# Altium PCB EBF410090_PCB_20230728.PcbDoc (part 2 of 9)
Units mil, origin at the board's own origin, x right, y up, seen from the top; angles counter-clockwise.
Board outline 5393.69 x 3858.26 mil, 6 copper layers (TOP, GND02, ART03, ART04, PWR05, BOTTOM), stack 47.2 mil thick; 570 components, 437 nets, 2015 pads, 1260 vias.
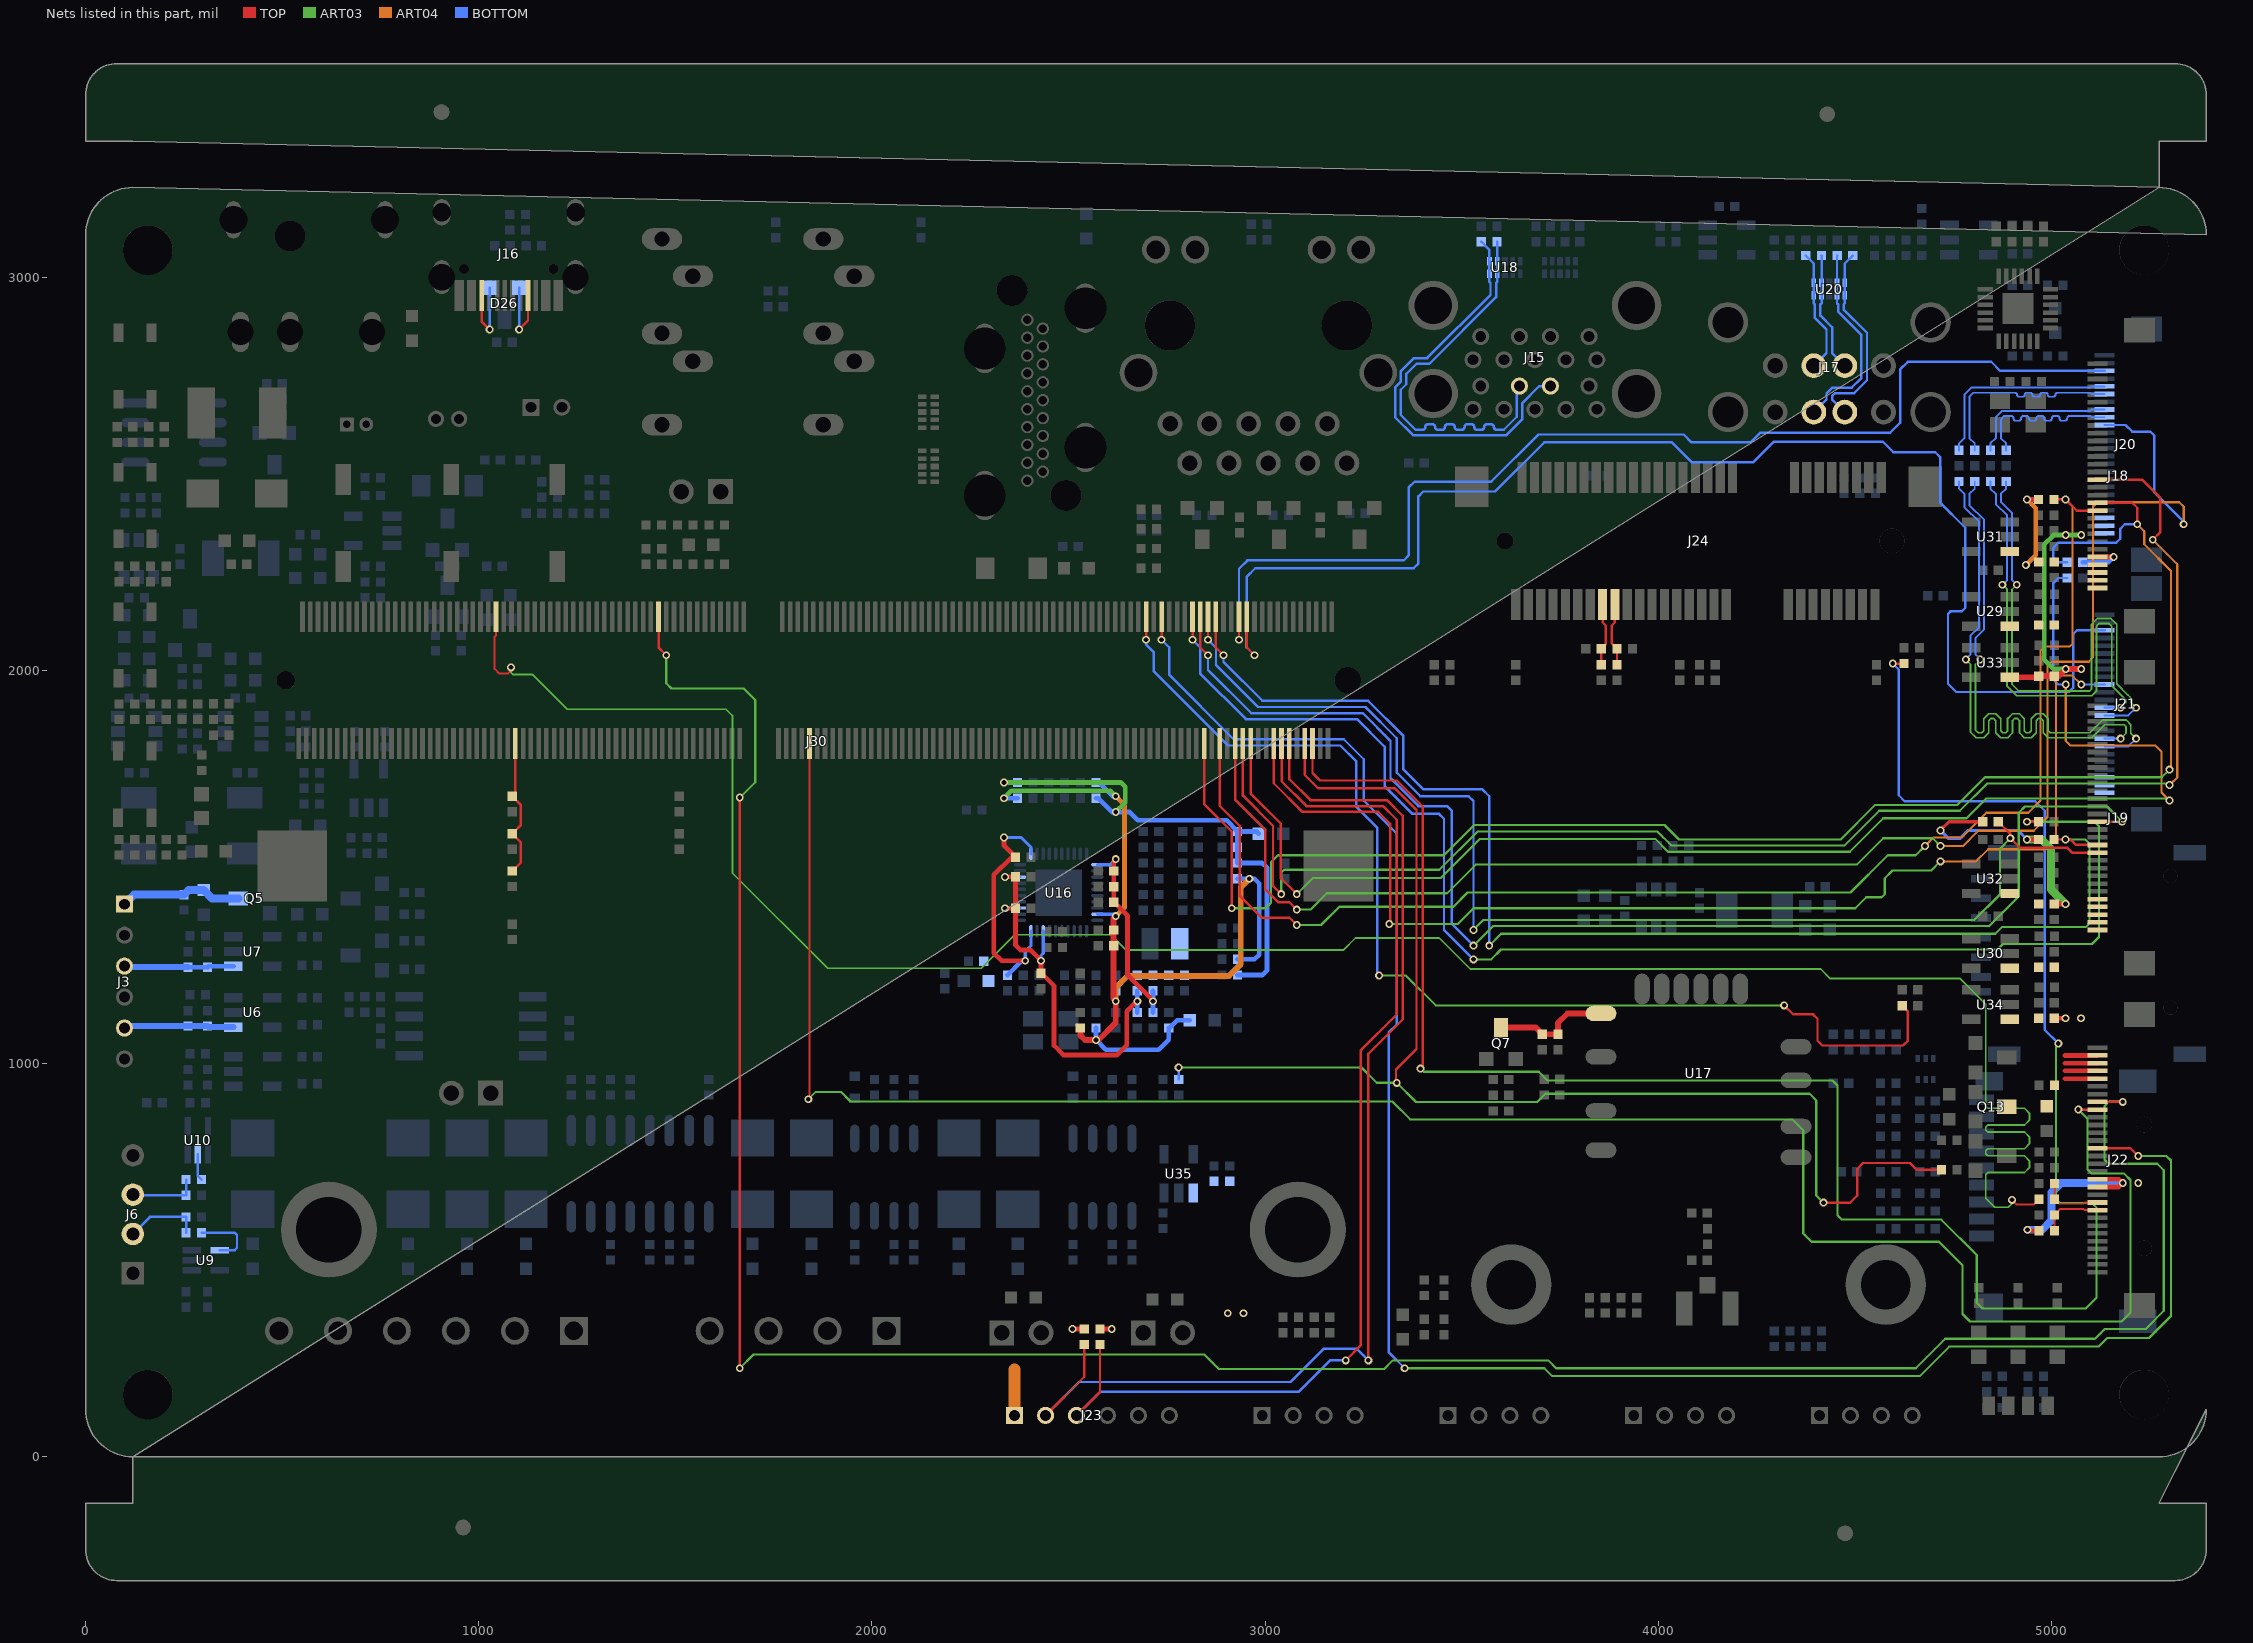
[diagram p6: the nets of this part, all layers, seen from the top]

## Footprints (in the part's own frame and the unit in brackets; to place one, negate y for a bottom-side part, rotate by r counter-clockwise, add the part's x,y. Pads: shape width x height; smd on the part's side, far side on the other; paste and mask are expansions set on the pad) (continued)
DB2ERC-3P81-4P [mil] "DB2ERC-3P81-4P"
  rect 70.87x70.87 / inner round 60 / far side rect 70.87x70.87 hole 47.24: 1(-225.39,-137.79)
  round 70.87 / inner round 60 / far side round 70.87 hole 47.24: 2(-75.39,-137.79) 3(74.61,-137.79) 4(224.61,-137.79)
  silkscreen extent -354,-181 319,179, body extent -323,-185 323,185, height 150
DB2ERC-3P81-6P [mil] "DB2ERC-3P81-6P"
  rect 70.87x70.87 / inner round 60 / far side rect 70.87x70.87 hole 47.24: 1(-375,-137.79)
  round 70.87 hole 47.24: 2(-225,-137.79) 5(225,-137.79)
  round 70.87 / inner round 60 / far side round 70.87 hole 47.24: 3(-75,-137.79) 4(75,-137.79) 6(375,-137.79)
  silkscreen extent -503,-181 470,179, body extent -472,-185 472,185, height 150
DC_IN_TH_3P_10R1X11R6 [mil] "DC_IN_TH_3P_10R1X11R6"
  oval 94.5x39.4 hole 70.9 slot 15.7 at 90 deg: 1(-111.25,-194.9) 5(-111.25,190.9)
  oval 102.4x43.3 hole 66.9 slot 19.7 at 90 deg: 2(174.25,-51.2) 3(174.25,157.4)
  oval 102.4x43.3 / inner round 60 / far side oval 102.4x43.3 hole 66.9 slot 19.7 at 90 deg: 4(174.25,-177.2)
  round 78.7 hole 78.7 unplated: ""(-69.85,-51.2)
  silkscreen extent -232,-201 226,197, body extent -237,-228 237,228, height 150
EAR_JACK [mm] "EAR_JACK"
  oval 1.4x2.6 / inner round 1.524 / far side oval 1.4x2.6 hole 1 slot 2 at 90 deg: 1(-5.904,-0.05) 2(-3.504,1.95) 3(1.996,1.95) 4(6.096,-0.05) 5(0.196,-0.05)
  silkscreen extent -11.12,-4.06 7.2,4.06, body extent -7.2,-4.15 7.2,4.15, height 3.81
EC6P3 [mil] "EC6P3"
  rect 39.4x78.7 smd: 1(0,110.24) 2(0,-110.24)
  silkscreen extent -130,-130 130,130, body extent -138,-157 138,157, height 150
ES0402#1 [mil] "ES0402"
  rect 23.6x23.6 smd: 1(-19.68,0) 2(19.68,0)
  silkscreen extent -37,-17 37,17, body extent -37,-17 37,17, height 150
ES0402#2 [mil] "ES0402"
  rect 23.6x23.6 smd: 1(19.68,0) 2(-19.68,0)
  silkscreen extent -37,-17 37,17, body extent -37,-17 37,17, height 150
F1812 [mil] "F1812"
  rect 70.08x129.92 smd: 1(-90.75,0) 2(90.75,0)
  silkscreen extent -134,-75 134,75
FPC-30P-0P5 [mm] "FPC-30P-0P5"
  rect 0.3x1.3 smd: 1(-7.25,2.733) 2(-6.75,2.733) 3(-6.25,2.733) 4(-5.75,2.733) 5(-5.25,2.733) 6(-4.75,2.733) 7(-4.25,2.733) 8(-3.75,2.733) 9(-3.25,2.733) 10(-2.75,2.733) 11(-2.25,2.733) 12(-1.75,2.733) 13(-1.25,2.733) 14(-0.75,2.733) 15(-0.25,2.733) 16(0.25,2.733) 17(0.75,2.733) 18(1.25,2.733) 19(1.75,2.733) 20(2.25,2.733) 21(2.75,2.733) 22(3.25,2.733) 23(3.75,2.733) 24(4.25,2.733) 25(4.75,2.733) 26(5.25,2.733) 27(5.75,2.733) 28(6.25,2.733) 29(6.75,2.733) 30(7.25,2.733)
  rect 1.6x2 smd: 31(9.4,0.033) 32(-9.4,0.033)
  silkscreen extent -10.05,-3.27 10.05,4.14, body extent -10.05,-3.35 10.05,3.35, height 3.81
FPC_24P_0P5 [mm] "FPC_24P_0P5"
  rect 0.3x1.3 smd: 1(-5.75,-2.701) 2(-5.25,-2.701) 3(-4.75,-2.701) 4(-4.25,-2.701) 5(-3.75,-2.701) 6(-3.25,-2.701) 7(-2.75,-2.701) 8(-2.25,-2.701) 9(-1.75,-2.701) 10(-1.25,-2.701) 11(-0.75,-2.701) 12(-0.25,-2.701) 13(0.25,-2.701) 14(0.75,-2.701) 15(1.25,-2.701) 16(1.75,-2.701) 17(2.25,-2.701) 18(2.75,-2.701) 19(3.25,-2.701) 20(3.75,-2.701) 21(4.25,-2.701) 22(4.75,-2.701) 23(5.25,-2.701) 24(5.75,-2.701)
  rect 1.6x2 smd: 25(7.45,0.001) 26(-7.45,0.001)
  silkscreen extent -8.1,-3.95 8.1,3.35
GH1P25_TH_2P [mil] "GH1P25_TH_2P"
  rect 35.43x35.43 / inner round 60 / far side rect 35.43x35.43 hole 19.69: 1(-24.65,-33.42)
  round 35.43 hole 19.69: 2(24.57,-33.42)
  silkscreen extent -87,-69 87,69
HDMI-SMD [mil] "HDMI-SMD"
  round 31.5 / inner round 60 / far side round 31.5 hole 21.65: 1(50.23,19.69) 3(4.76,19.69) 4(-17.68,-19.68) 6(-63.19,-19.68) 7(-86.18,19.69) 9(-131.65,19.69) 10(-154.21,-19.68) 12(-199.72,-19.68) 13(-222.6,19.69) 14(-245.23,-19.68) 15(-268.08,19.69) 16(-290.75,-19.68) 18(-336.26,-19.68) 19(-359.01,19.69)
  round 31.5 hole 21.65: 2(27.84,-19.68) 5(-40.71,19.69) 8(-108.7,-19.68) 11(-177.13,19.69) 17(-313.54,19.69)
  oval 125.98x55.12 / inner round 60 / far side oval 125.98x55.12 hole 106.3 slot 35.43 at 90 deg: G1(-396.62,127.96) G2(-22.6,127.96) G3(-274.57,-127.95) G4(79.77,-127.95)
  round 78.7 hole 78.7 unplated: ""(-396.62,-78.74) ""(125.03,59.06)
  silkscreen extent -450,-151 465,149, body extent -464,-160 464,160, height 150
HDR1X2-2R54-TM-VM#1 [mm] "HDR1X2-2R54-TM-VM"
  rect 1.6x1.6 hole 1: 1(1.27,0)
  round 1.6 / inner round 1.524 / far side round 1.6 hole 1: 2(-1.27,0)
  silkscreen extent -2.54,-1.25 2.54,1.25, body extent -2.54,-1.25 2.54,1.25, height 3.81
HDR1X2-2R54-TM-VM#2 [mm] "HDR1X2-2R54-TM-VM"
  rect 1.6x1.6 / inner round 1.524 / far side rect 1.6x1.6 hole 1: 1(-1.27,0)
  round 1.6 / inner round 1.524 / far side round 1.6 hole 1: 2(1.27,0)
  silkscreen extent -2.54,-1.25 2.54,1.25, body extent -2.54,-1.25 2.54,1.25, height 3.81
HY911130A [mm] "HY911130A"
  round 1.6 / inner round 1.524 / far side round 1.6 hole 1: 1(5.72,-8.79) 2(4.45,-6.25) 3(3.18,-8.79) 4(1.91,-6.25) 5(0.64,-8.79) 6(-0.63,-6.25) 7(-1.9,-8.79) 8(-3.17,-6.25) 9(-4.44,-8.79)
  round 1.6 hole 1: 10(-5.71,-6.25)
  round 1.8 / inner round 1.524 / far side round 1.8 hole 1.2: 11(6.625,5) 12(4.085,5) 13(-4.085,5) 14(-6.625,5)
  round 2.43 hole 1.83: 15(7.745,-2.95) 16(-7.745,-2.95)
  round 3.25 hole 3.25 unplated: ""(-5.715,0.1) ""(5.715,0.1)
  silkscreen extent -8.02,-10.3 8.02,11, body extent -9.2,-11.1 9.2,11.1, height 3.81
L0603#1 [mil] "L0603"
  rect 31.5x31.5 smd: 1(-31.5,0) 2(31.5,0)
  silkscreen extent -54,-24 55,24, body extent -47,-16 47,16, height 150
L0603#2 [mil] "L0603"
  rect 31.5x31.5 smd: 1(31.5,0) 2(-31.5,0)
  silkscreen extent -55,-24 54,24, body extent -47,-16 47,16, height 150
L2520 [mil] "L2520"
  rect 44x80 smd: 1(-37.75,0) 2(37.75,0)
  silkscreen extent -68,-48 68,48, body extent -65,-45 65,45, height 150
L4520 [mil] "L4520"
  rect 55.12x90.55 smd: 1(-70.97,-0.1) 2(70.77,-0.1)
  silkscreen extent -91,-87 90,87, body extent -91,-87 91,87, height 150
LED0603 [mil] "LED0603"
  rect 36.61x38.58 smd: 1(30.32,0) 2(-30.31,0)
  silkscreen extent -60,-31 80,31, body extent -49,-19 49,19, height 150
MARK#1 [mil] "MARK"
  round 40 smd: 1(0,0) 1(3571,3616)
  round 40 smd far side: 1(0,1) 1(55,3601) 1(3525,6) 1(3570,3616)
  body extent -40,-40 3611,3656, height 150
MARK#2 [mil] "MARK"
  round 40 smd: 1(-55,-3601) 1(3516,15)
  round 40 smd far side: 1(-55,-3600) 1(0,0) 1(3470,-3595) 1(3515,15)
  body extent -95,-3641 3556,55, height 150
MARK#3 [mil] "MARK"
  round 40 smd: 1(-3525,-6) 1(46,3610)
  round 40 smd far side: 1(-3525,-5) 1(-3470,3595) 1(0,0) 1(45,3610)
  body extent -3565,-46 86,3650, height 150
MARK#4 [mil] "MARK"
  round 40 smd: 1(-3571,-3616) 1(0,0)
  round 40 smd far side: 1(-3571,-3615) 1(-3516,-15) 1(-46,-3610) 1(-1,0)
  body extent -3611,-3656 40,40, height 150
MARK#5 [mil] "MARK"
  round 40 smd: 1(-3570,3615) 1(-3515,15) 1(-45,3610) 1(0,0)
  round 40 smd far side: 1(-3570,3616) 1(1,0)
  body extent -3610,-40 41,3656, height 150
MARK#6 [mil] "MARK"
  round 40 smd: 1(-55,3600) 1(0,0) 1(3470,3595) 1(3515,-15)
  round 40 smd far side: 1(-55,3601) 1(3516,-15)
  body extent -95,-55 3556,3641, height 150
MARK#7 [mil] "MARK"
  round 40 smd: 1(-3525,5) 1(-3470,-3595) 1(0,0) 1(45,-3610)
  round 40 smd far side: 1(-3525,6) 1(46,-3610)
  body extent -3565,-3650 86,46, height 150
MARK#8 [mil] "MARK"
  round 40 smd: 1(0,0) 1(55,-3600) 1(3525,-5) 1(3570,-3615)
  round 40 smd far side: 1(0,1) 1(3571,-3615)
  body extent -40,-3655 3611,41, height 150
NANO_SIM [mm] "NANO_SIM"
  rect 0.5x1.3 smd: 1(0.25,6.94) 2(-2.29,6.94) 3(-4.83,6.94) 4(2.47,6.94) 5(1.52,6.94) 6(-1.02,6.94) 7(-3.56,6.94)
  rect 1x2.1 smd: 8(-6.5,5.46) 9(6.5,5.46) 10(-6.5,-6.54) 11(6.5,-6.54)
  round 0.9 hole 0.9 unplated: ""(-5,-5.29) ""(3.5,-5.29)
  silkscreen extent -6.15,-7.6 6.15,5.9, body extent -7.05,-7.64 7.05,7.64, height 3.81
NPTH_M3 [mil] "NPTH_M3"
  round 125.98 / inner round 60 / far side round 125.98 hole 125.98 unplated: 1(0,0)
  body extent -122,-122 122,122, height 150
PCIE_52P [mm] "PCIE_52P"
  rect 0.6x2 smd: 1(-11.8,-4.1) 2(-11.4,4.1) 3(-11,-4.1) 4(-10.6,4.1) 5(-10.2,-4.1) 6(-9.8,4.1) 7(-9.4,-4.1) 8(-9,4.1) 9(-8.6,-4.1) 10(-8.2,4.1) 11(-7.8,-4.1) 12(-7.4,4.1) 13(-7,-4.1) 14(-6.6,4.1) 15(-6.2,-4.1) 16(-5.8,4.1) 17(-2.2,-4.1) 18(-1.8,4.1) 19(-1.4,-4.1) 20(-1,4.1) 21(-0.6,-4.1) 22(-0.2,4.1) 23(0.2,-4.1) 24(0.6,4.1) 25(1,-4.1) 26(1.4,4.1) 27(1.8,-4.1) 28(2.2,4.1) 29(2.6,-4.1) 30(3,4.1) 31(3.4,-4.1) 32(3.8,4.1) 33(4.2,-4.1) 34(4.6,4.1) 35(5,-4.1) 36(5.4,4.1) 37(5.8,-4.1) 38(6.2,4.1) 39(6.6,-4.1) 40(7,4.1) 41(7.4,-4.1) 42(7.8,4.1) 43(8.2,-4.1) 44(8.6,4.1) 45(9,-4.1) 46(9.4,4.1) 47(9.8,-4.1) 48(10.2,4.1) 49(10.6,-4.1) 50(11,4.1) 51(11.4,-4.1) 52(11.8,4.1)
  rect 2.15x2.6 smd: 53(14.65,-3.5) 54(-14.65,-3.5)
  round 1.6 hole 1.6 unplated: ""(-12.5,0)
  round 1.1 hole 1.1 unplated: ""(12.5,0)
  silkscreen extent -15,-4.6 15,50.95, body extent -15.8,-5.2 15.8,5.2, height 3.81
PH-1X2-2P0_L [mm] "PH-1X2-2P0_L"
  rect 1.1x1.1 / inner round 1.524 / far side rect 1.1x1.1 hole 0.7: 1(-1,-0.6)
  round 1.1 / inner round 1.524 / far side round 1.1 hole 0.7: 2(1,-0.6)
  silkscreen extent -3,-2.6 3,2.6, body extent -3.1,-2.7 3.1,2.7, height 3.81
PH-1X4-2P0 [mm] "PH-1X4-2P0"
  rect 1.1x1.1 / inner round 1.524 / far side rect 1.1x1.1 hole 0.7: 1(-3,-0.6)
  round 1.1 / inner round 1.524 / far side round 1.1 hole 0.7: 2(-1,-0.6) 3(1,-0.6)
  round 1.1 hole 0.7: 4(3,-0.6)
  silkscreen extent -5,-2.6 5,2.6, body extent -5.1,-2.7 5.1,2.7, height 3.81
PH-1X6-2P0#1 [mm] "PH-1X6-2P0"
  rect 1.1x1.1 / inner round 1.524 / far side rect 1.1x1.1 hole 0.7: 1(-5,-0.6)
  round 1.1 hole 0.7: 2(-3,-0.6) 4(1,-0.6) 6(5,-0.6)
  round 1.1 / inner round 1.524 / far side round 1.1 hole 0.7: 3(-1,-0.6) 5(3,-0.6)
  silkscreen extent -7,-2.6 7,2.6, body extent -7.1,-2.7 7.1,2.7, height 3.81
PH-1X6-2P0#2 [mm] "PH-1X6-2P0"
  rect 1.1x1.1 / inner round 1.524 / far side rect 1.1x1.1 hole 0.7: 1(-5,-0.6)
  round 1.1 / inner round 1.524 / far side round 1.1 hole 0.7: 2(-3,-0.6) 3(-1,-0.6) 4(1,-0.6) 5(3,-0.6)
  round 1.1 hole 0.7: 6(5,-0.6)
  silkscreen extent -7,-2.6 7,2.6, body extent -7.1,-2.7 7.1,2.7, height 3.81
QFN24 [mm] "QFN24"
  rect 1x0.3 smd: 1(-2.1,1.25) 2(-2.1,0.75) 3(-2.1,0.25) 4(-2.1,-0.25) 5(-2.1,-0.75) 6(-2.1,-1.25) 13(2.1,-1.25) 14(2.1,-0.75) 15(2.1,-0.25) 16(2.1,0.25) 17(2.1,0.75) 18(2.1,1.25)
  rect 0.3x1 smd: 7(-1.25,-2.1) 8(-0.75,-2.1) 9(-0.25,-2.1) 10(0.25,-2.1) 11(0.75,-2.1) 12(1.25,-2.1) 19(1.25,2.1) 20(0.75,2.1) 21(0.25,2.1) 22(-0.25,2.1) 23(-0.75,2.1) 24(-1.25,2.1)
  rect 2x2 smd: 25(0,0)
  silkscreen extent -2.79,-2.1 2.1,2.1, body extent -2.7,-2.7 2.7,2.7, height 3.81
QFP_40P_R [mil] "QFP_40P_R"
  oval 31.5x8.66 smd: 1(-98.43,70.87) 2(-98.43,55.12) 3(-98.43,39.37) 4(-98.43,23.62) 5(-98.43,7.87) 6(-98.43,-7.87) 7(-98.43,-23.62) 8(-98.43,-39.37) 9(-98.43,-55.12) 10(-98.43,-70.87) 21(98.43,-70.87) 22(98.43,-55.12) 23(98.43,-39.37) 24(98.43,-23.62) 25(98.43,-7.87) 26(98.43,7.87) 27(98.43,23.62) 28(98.43,39.37) 29(98.43,55.12) 30(98.43,70.87)
  oval 8.66x31.5 smd: 11(-70.87,-98.43) 12(-55.12,-98.43) 13(-39.37,-98.43) 14(-23.62,-98.43) 15(-7.87,-98.43) 16(7.87,-98.43) 17(23.62,-98.43) 18(39.37,-98.43) 19(55.12,-98.43) 20(70.87,-98.43) 31(70.87,98.43) 32(55.12,98.43) 33(39.37,98.43) 34(23.62,98.43) 35(7.87,98.43) 36(-7.87,98.43) 37(-23.62,98.43) 38(-39.37,98.43) 39(-55.12,98.43) 40(-70.87,98.43)
  rect 118.11x118.11 smd: 41(0,0)
  silkscreen extent -130,-98 98,110, body extent -116,-116 116,116, height 150
R0402#1 [mil] "R0402"
  rect 23.6x23.6 smd: 1(19.68,0) 2(-19.68,0)
  silkscreen extent -37,-17 37,17, body extent -37,-17 37,17, height 150
R0402#2 [mil] "R0402"
  rect 23.6x23.6 smd: 1(-19.68,0) 2(19.68,0)
  silkscreen extent -37,-17 37,17, body extent -37,-17 37,17, height 150
R0603#1 [mil] "R0603"
  rect 31.5x31.5 smd: 1(-31.5,0) 2(31.5,0)
  silkscreen extent -54,-24 55,24
R0603#2 [mil] "R0603"
  rect 31.5x31.5 smd: 1(31.5,0) 2(-31.5,0)
  silkscreen extent -55,-24 54,24, body extent -47,-16 47,16, height 150
RL-UM02WBS-8723BU [mm] "RL-UM02WBS-8723BU"
  oval 2x1 smd: 1(-6.3,4.122) 2(-6.3,2.122) 3(-6.3,-0.858) 4(-6.3,-3.018) 5(6.3,3.652) 6(6.3,1.122) 7(6.3,-2.378) 8(6.3,-5.178)
  oval 1x2 smd: 9(3.65,-6.748) 10(2.38,-6.748) 11(1.11,-6.748) 12(-0.16,-6.748) 13(-1.43,-6.748) 14(-2.7,-6.748)
  silkscreen extent -6.1,-6.55 6.1,6.45, body extent -6.1,-6.45 6.1,6.45, height 3.81
SMA214-CA [mil] "SMA214-CA"
  rect 82.68x70.87 smd: 1(-86.61,0) 2(86.61,0)
  silkscreen extent -87,-51 87,51, body extent -130,-55 130,55, height 150
SMB-CA [mil] "SMB-CA"
  rect 94.49x110.24 smd: 1(-90.55,0) 2(90.55,0)
  silkscreen extent -91,-71 91,71, body extent -138,-71 138,71, height 150
SMD4-6R80X2R50 [mil] "SMD4-6R80X2R50"
  rect 31.5x47.24 smd: 1(75,-27.56) 2(25,-27.56) 3(-25,-27.56) 4(-75,-27.56)
  silkscreen extent -134,-88 134,51, body extent -142,-59 142,59, height 150
SMTSO-M2R5 [mil] "SMTSO-M2R5"
  round 244.09 / inner round 204.72 / far side round 204.72 hole 166.14: 1(0,0)
  body extent -126,-126 126,126, height 150
SOD523 [mil] "SOD523"
  rect 23.62x27.56 smd: 1(-27.95,0) 2(27.95,0)
  silkscreen extent -51,-20 24,20, body extent -43,-16 43,16, height 150
SOD-123 [mil] "SOD-123"
  rect 47.24x55.12 smd: 1(66.93,0) 2(-66.93,0)
  silkscreen extent -71,-35 71,35, body extent -94,-39 94,39, height 150
SOIC8-208 [mil] "SOIC8-208"
  rect 70x25 smd: 1(157.48,-75) 2(157.48,-25) 3(157.48,25) 4(157.48,75) 5(-157.48,75) 6(-157.48,25) 7(-157.48,-25) 8(-157.48,-75)
  silkscreen extent -100,-104 224,104, body extent -197,-110 197,110, height 150
SOIC16 [mil] "SOIC16"
  oval 80x24 smd: 1(-109.8,174.8) 2(-109.8,125.2) 3(-109.8,74.8) 4(-109.8,25.2) 5(-109.8,-25.2) 6(-109.8,-74.8) 7(-109.8,-125.2) 8(-109.8,-174.8) 9(109.8,-174.8) 10(109.8,-125.2) 11(109.8,-74.8) 12(109.8,-25.2) 13(109.8,25.2) 14(109.8,74.8) 15(109.8,125.2) 16(109.8,174.8)
  silkscreen extent -179,-197 59,197, body extent -157,-205 157,205, height 150
SOP8#1 [mil] "SOP8"
  oval 23.62x70.87 smd: 1(-75,-98.43) 2(-25,-98.43) 3(25,-98.43) 4(75,-98.43) 5(75,98.43) 6(25,98.43) 7(-25,98.43) 8(-75,98.43)
  silkscreen extent -98,-164 98,55, body extent -98,-138 98,138, height 150
SOP8#2 [mil] "SOP8"
  oval 23.62x70.87 smd: 1(75,98.43) 2(25,98.43) 3(-25,98.43) 4(-75,98.43) 5(-75,-98.43) 6(-25,-98.43) 7(25,-98.43) 8(75,-98.43)
  silkscreen extent -98,-55 114,141, body extent -98,-138 98,138, height 150
SOT23#1 [mil] "SOT23"
  rect 36x36 smd: 1(-37.5,-43.5) 2(37.5,-43.5)
  rect 36x50 smd: 3(0,36.5)
  silkscreen extent -55,-54 55,36, body extent -56,-62 56,62, height 150
SOT23#2 [mil] "SOT23"
  rect 36x36 smd: 1(37.5,43.5) 2(-37.5,43.5)
  rect 36x50 smd: 3(0,-36.5)
  silkscreen extent -55,-36 55,54, body extent -56,-62 56,62, height 150
SOT23-5#1 [mil] "SOT23-5"
  rect 23.6x47.2 smd: 1(-37.4,-49.21) 2(0,-49.21) 3(37.4,-49.21) 4(37.4,49.21) 5(-37.4,49.21)
  silkscreen extent -70,-80 59,35, body extent -63,-75 63,75, height 150
SOT23-5#2 [mil] "SOT23-5"
  rect 23.6x47.2 smd: 1(37.4,49.21) 2(0,49.21) 3(-37.4,49.21) 4(-37.4,-49.21) 5(37.4,-49.21)
  silkscreen extent -59,-35 59,101, body extent -63,-75 63,75, height 150
SOT23_6#1 [mil] "SOT23_6"
  rect 27.56x35.43 smd: 1(-37.4,-47.24) 2(0,-47.24) 3(37.4,-47.24) 4(37.4,47.24) 5(0,47.24) 6(-37.4,47.24)
  silkscreen extent -75,-60 55,24
SOT23_6#2 [mil] "SOT23_6"
  rect 27.56x35.43 smd: 1(37.4,47.24) 2(0,47.24) 3(-37.4,47.24) 4(-37.4,-47.24) 5(0,-47.24) 6(37.4,-47.24)
  silkscreen extent -55,-24 86,49, body extent -55,-47 55,47, height 150
SOT563 [mil] "SOT563"
  rect 11.81x17.72 smd: 1(19.65,25.58) 2(-0.04,25.58) 3(-19.73,25.58) 4(-19.73,-27.56) 5(-0.04,-27.56) 6(19.65,-27.56)
  silkscreen extent -34,-33 67,37, body extent -32,-38 32,38, height 150
SOT-353#1 [mil] "SOT-353"
  rect 16x47 smd: 1(-25.91,-35.43) 2(-0.32,-35.43) 3(25.27,-35.43) 4(25.27,35.43) 5(-25.91,35.43)
  silkscreen extent -55,-80 45,70, body extent -40,-65 40,65, height 150
SOT-353#2 [mil] "SOT-353"
  rect 16x47 smd: 1(25.9,35.43) 2(0.31,35.43) 3(-25.28,35.43) 4(-25.28,-35.43) 5(25.9,-35.43)
  silkscreen extent -45,-70 55,80, body extent -40,-65 40,65, height 150
SW4-4R20X3R25-SM [mm] "SW4-4R20X3R25-SM"
  rect 1.2x0.65 smd: 1(-2.15,1.075) 2(2.15,1.075) 3(2.15,-1.075) 4(-2.15,-1.075)
  silkscreen extent -2.1,-1.6 2.1,1.6, body extent -2.8,-1.7 2.8,1.7, height 3.81
T3R2-5R2_TOPSMT [mil] "T3R2-5R2_TOPSMT"
  round 204.72 hole 125.98: 1(0,0)
  body extent -108,-108 108,108, height 150
TFCARD [mil] "TFCARD"
  rect 27.56x62.99 smd: 1(88.58,206.83) 2(45.27,206.83) 3(1.97,206.83) 4(-41.34,206.83) 5(-84.65,206.83) 6(-127.95,206.83) 7(-171.26,206.83) 8(-214.57,206.83) 9(-257.88,206.83)
  rect 47.24x70 smd: 10(-305.12,187.14)
  rect 60x95 smd: 11(-305.12,-190.81) 12(305.12,-190.81)
  rect 70x70 smd: 13(269.68,187.14)
  round 40 hole 40 unplated: ""(-194.88,-206.56) ""(120.08,-206.56)
  silkscreen extent -289,-365 281,179, body extent -335,-238 335,238, height 150
TYPE-C-31-M-12 [mm] "TYPE-C-31-M-12"
  rect 0.3x2 smd: A1(-3.35,3.539) A4(-2.55,3.539) A5(-1.25,3.539) A6(-0.249,3.539) A7(0.249,3.539) A8(1.25,3.539) A9(2.55,3.539) A12(3.35,3.539) B1(3.051,3.539) B4(2.25,3.539) B5(1.75,3.539) B6(0.749,3.539) B7(-0.749,3.539) B8(-1.75,3.539) B9(-2.25,3.539) B12(-3.051,3.539)
  oval 1.1x1.7 / inner round 1.524 / far side oval 1.1x1.7 hole 1.2 slot 0.6 at 0 deg: C1(-4.321,-1.84) C2(4.321,-1.84)
  oval 1.1x2.2 / inner round 1.524 / far side oval 1.1x2.2 hole 1.7 slot 0.6 at 0 deg: C3(-4.321,2.351) C4(4.321,2.351)
  round 0.65 hole 0.65 unplated: ""(-2.891,1.82) ""(2.891,1.82)
  silkscreen extent -4.5,-4.43 4.5,2.86, body extent -4.87,-4.54 4.87,4.54, height 3.81
UFL-3 [mil] "UFL-3"
  rect 41.34x41.34 smd: 1(0,-40.86)
  rect 41.34x86.61 smd: 2(-59.06,18.2) 3(59.06,18.2)
  body extent -80,-62 80,62, height 150
USB3D0-AF-18P [mm] "USB3D0-AF-18P"
  round 1.1 / inner round 1.524 / far side round 1.1 hole 0.7: 1(-3.5,2.9) 2(-1,2.9) 3(1,2.9) 5(4,4.4) 6(2,4.4) 8(-2,4.4) 9(-4,4.4) 10(-3.5,6.1) 11(-1,6.1) 12(1,6.1) 14(4,7.6) 15(2,7.6) 17(-2,7.6) 18(-4,7.6)
  round 1.1 hole 0.7: 4(3.5,2.9) 7(0,4.4) 13(3.5,6.1) 16(0,7.6)
  round 3.2 hole 2.4: 19(6.57,0.9) 20(6.57,6.58) 21(-6.57,6.58) 22(-6.57,0.9)
  silkscreen extent -7.26,-8.74 7.19,8.77, body extent -8.4,-8.8 8.4,8.8, height 3.81
USB-A-D [mm] "USB-A-D"
  round 1.6 / inner round 1.524 / far side round 1.6 hole 1: 1(3.45,-7.425) 2(0.95,-7.425) 3(-1.05,-7.425) 7(3.45,-4.425) 8(0.95,-4.425) 9(-1.05,-4.425)
  round 1.6 hole 1: 4(-3.55,-7.425) 10(-3.55,-4.425)
  round 2.6 hole 2: 5(-6.6,-7.425) 6(6.5,-7.425) 11(-6.6,-1.625) 12(6.5,-1.625)
  silkscreen extent -6.65,-8.42 6.55,9.08, body extent -7.75,-9.07 7.75,9.08, height 3.81
USON_10#1 [mm] "USON_10"
  rect 0.3x0.55 smd: 1(1,0.4) 2(0.5,0.4) 4(-0.5,0.4) 5(-1,0.4) 6(-1,-0.4) 7(-0.5,-0.4) 9(0.5,-0.4) 10(1,-0.4)
  rect 0.4x0.55 smd: 3(0,0.4) 8(0,-0.4)
  silkscreen extent -1.3,-0.5 1.95,0.95, body extent -1.3,-0.7 1.3,0.7, height 3.81
USON_10#2 [mm] "USON_10"
  rect 0.3x0.55 smd: 1(-1,-0.4) 2(-0.5,-0.4) 4(0.5,-0.4) 5(1,-0.4) 6(1,0.4) 7(0.5,0.4) 9(-0.5,0.4) 10(-1,0.4)
  rect 0.4x0.55 smd: 3(0,-0.4) 8(0,0.4)
  silkscreen extent -1.95,-0.95 1.3,0.5, body extent -1.3,-0.7 1.3,0.7, height 3.81
XH2P54-4P [mil] "XH2P54-4P"
  rect 57.09x57.09 / inner round 60 / far side rect 57.09x57.09 hole 33.46: 1(-150,20)
  round 57.09 / inner round 60 / far side round 57.09 hole 33.46: 2(-50,20) 3(50,20)
  round 57.09 hole 33.46: 4(150,20)
  silkscreen extent -256,-119 256,120, body extent -255,-120 255,120, height 150
ZH1P5MM_TH_2P [mm] "ZH1P5MM_TH_2P"
  round 1.05 / inner round 1.524 / far side round 1.05 hole 0.65: 1(-0.75,0.65)
  round 1.05 hole 0.65: 2(0.75,0.65)
  silkscreen extent -2.25,-1.85 2.25,1.85, body extent -2.2,-1.85 2.2,1.85, height 3.81

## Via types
v1: diameter 20, hole 12, TOP to BOTTOM, 1260 vias

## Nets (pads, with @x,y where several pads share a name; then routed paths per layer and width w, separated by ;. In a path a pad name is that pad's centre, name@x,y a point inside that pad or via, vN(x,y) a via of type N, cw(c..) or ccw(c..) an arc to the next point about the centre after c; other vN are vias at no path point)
1V05_AVDD_PHY: C99.1 C100.1 C101.1 C102.1 R124.2 U16.3 U16.8 U16.38 | length 1077.7
  TOP w12: v1(2338.52,1395) C101.1@2365.32,1395 ; v1(2338.52,1474.81) 2339.81,1474.81 2340,1475 C99.1@2365.32,1475 C101.1@2365.32,1395 ; v1(2675,1158.52) 2673.52,1158.52 2648,1133 2648,1046 2624,1022 2487,1022 2463,1046 2463,1197.9 2431.22,1229.68 C100.1@2430,1229.68 v1(2430,1261.48) 2402.48,1289 2377.32,1289 2365.32,1301 C101.1@2365.32,1395
  BOTTOM w8: v1(2338.52,1395) 2340.26,1395 2340.89,1395.63 U16.3@2376.57,1395.63 ; v1(2338.52,1474.81) 2340.19,1474.81 2340.63,1474.37 U16.8@2376.57,1474.37 ; v1(2430,1261.48) 2430,1275 2435.63,1280.63 U16.38@2435.63,1336.57
  BOTTOM w12: C102.1@2675,1129.68 v1(2675,1158.52) R124.2@2675,1185.32
1V05_DVDD_PHY: C95.1 C96.1 C97.1 C98.1 R123.1 U16.21 | length 514.1
  TOP w12: v1(2620,1520) 2614.68,1514.68 C97.1@2614.68,1490 C96.1@2614.68,1450 C95.1@2614.68,1410 2616.12,1410 2650,1376.12 2650,1225 2715,1160 v1(2715,1158.52)
  BOTTOM w8: U16.21@2573.43,1505.87 2605.87,1505.87 v1(2620,1520)
  BOTTOM w12: C98.1@2715,1129.68 v1(2715,1158.52) R123.1@2715,1185.32
1V05_PHY: C81.1 C82.1 L4.2 R123.2 R124.1
1V8_DVDD_PHY: C103.1 C104.1 L7.1 R89.2 R90.1 R106.1 R119.1 | length 1375
  ART03 w12: v1(2335.63,1715) 2633,1715 2644,1704 2644,1664 v1(2620,1640)
  BOTTOM w12: v1(2335.63,1715) R119.1@2370.32,1715 ; R106.1@2569.68,1675 2575,1675 2610,1640 v1(2620,1640) 2655,1640 2676,1619 2901.9,1619 2929.68,1591.22 C103.1@2929.68,1590 ; R89.2@2929.68,1225 2993,1225 3005,1237 3005,1498 2993,1510 R90.1@2929.68,1510 C104.1@2929.68,1550 C103.1@2929.68,1590 ; L7.1@2983.5,1585 2978.5,1590 C103.1@2929.68,1590
3V3_AVDD_PHY: C91.1 C92.1 C93.1 L6.1 U16.11 U16.40 | length 660.8
  TOP w12: v1(2335.63,1575) 2335.63,1554.69 C93.1@2365.32,1525 2354.99,1525 2310,1480.01 2310,1281 2329.52,1261.48 v1(2390,1261.48)
  BOTTOM w8: v1(2335.63,1575) 2380,1575 2404.13,1550.87 U16.11@2404.13,1533.43 ; v1(2390,1261.48) 2390,1285 2404.13,1299.13 U16.40@2404.13,1336.57
  BOTTOM w12: C92.1@2345,1224.68 2345,1225.26 2381.22,1261.48 v1(2390,1261.48)
3V3_DVDD_PHY: C87.1 C88.1 C89.1 L5.1 R91.2 R92.2 R107.2 R110.1 R118.2 R120.1 R122.2 U16.29 | length 2435.9
  TOP w15: R122.2@2530,1090.32 2530,1072 2542,1060 v1(2570,1060) 2576,1060 2620,1104 v1(2620,1158.52) 2620,1160 2614.68,1165.32 C88.1@2614.68,1300 C89.1@2614.68,1340 2614.68,1369.68 v1(2620,1375)
  ART03 w12: v1(2335.63,1675) 2354.63,1694 2606,1694 v1(2620,1680)
  ART04 w12: v1(2620,1375) 2642.14,1397.14 2642.14,1657.86 v1(2620,1680)
  ART04 w15: v1(2620,1158.52) 2620,1193 2650,1223 2908,1223 2938,1253 2938,1448 v1(2960,1470)
  BOTTOM w8: U16.29@2573.43,1379.88 2615.12,1379.88 v1(2620,1375)
  BOTTOM w12: v1(2335.63,1675) R120.1@2370.32,1675 ; R107.2@2569.68,1715 2577,1715 2612,1680 v1(2620,1680) ; R118.2@2570,1090.32 v1(2570,1060) 2595,1035 2729.37,1035 2755,1060.63 C87.1@2755,1090.32 2756.22,1090.32 2775.9,1110 L5.1@2808.5,1110 ; v1(2620,1158.52) R110.1@2620,1185.32 ; R92.2@2929.68,1265 2973,1265 2985,1277 2985,1458 2973,1470 v1(2960,1470) R91.2@2929.68,1470
3V3_EDP: C163.1 C164.1 J22.12 J22.13 J23.1 R189.1 R190.1 R191.1 U35.1 | length 676.8
  TOP w12: v1(2510,324.68) R190.1@2540,324.68 ; R191.1@2580,324.68 v1(2610,324.68) ; v1(4939.01,577.37) 4941.38,575 R189.1@4968.32,575 ; J22.12@5117.47,686.11 5171.46,686.11 v1(5181.46,696.11) 5171.78,705.79 J22.13@5117.47,705.79
  ART04 w30: J23.1@2362.72,105.01 2362.72,222.28
  BOTTOM w20: v1(4939.01,577.37) 4976.37,577.37 5000.37,601.37 5000.37,672.11 5024.37,696.11 v1(5181.46,696.11)
  other v1: 2905,365 2945,365 5220.83,696.11
3V3_IMAGE_1: C142.1 C143.1 J18.4 J18.5 R163.1 R167.1 U31.1 | length 340.7
  TOP w12: v1(4938,2435) R163.1@4967.32,2435 ; J18.5@5117.47,2288.31 v1(5158.31,2288.31)
  ART04 w12: v1(4935,2268.11) 4960,2293.11 4960,2413 v1(4938,2435)
  BOTTOM w12: R167.1@5079.68,2275 5145,2275 v1(5158.31,2288.31)
3V3_IMAGE_2: C144.1 C145.1 J19.4 J19.5 R165.1 R169.1 U32.1 | length 648.2
  TOP w8: v1(4717.63,1593) 4739.63,1615 R165.1@4825.32,1615
  TOP w12: v1(4938,1570) R169.1@4967.32,1570 ; C145.1@5007,1405.68 v1(5036,1405.68)
  ART03 w20: v1(4938,1570) 4975,1570 4999,1546 4999,1442.68 v1(5036,1405.68)
  BOTTOM w8: v1(4717.63,1593) 4737.63,1573 4768,1573 4788.01,1593.01 4914.99,1593.01 v1(4938,1570)
3V3_OUT: C42.1 C43.1 J3.5 U6.1 | length 280.2
  BOTTOM w15: J3.5@98.74,1090.32 103.74,1095.32 C43.1@260,1095.32 C42.1@310,1095.32 312.72,1092.6 U6.1@375.79,1092.6
3V3_WLAN: C110.1 C111.1 Q7.3 U17.8 | length 300.1
  TOP w15: Q7.3@3600,1091.5 3688.18,1091.5 C110.1@3705,1074.68 C111.1@3745,1074.68 3745,1103.46 3769.01,1127.47 U17.8@3854.39,1127.47
5V0_CAM_1: C151.1 C152.1 J20.1 J20.2 J20.3 U33.1 | length 691.4
  TOP w15: U33.1@4894.21,1982.6 4965.28,1982.6 C151.1@4968,1985.32 C152.1@5007,1985.32 5018.16,1985.32 v1(5036.42,2003.58) v1(5075.79,2003.58)
  ART03 w12: v1(5075.79,2003.58) v1(5036.42,2003.58) 5005.58,2003.58 4981.58,2027.58 4981.58,2320.37 5005.58,2344.37 v1(5036.42,2344.37) v1(5075.79,2344.37)
5V0_CAM_2: C154.1 C155.1 J21.1 J21.2 J21.3 U34.1 | length 29
  TOP w12: C155.1@5007,1115.32 v1(5036,1115.32)
  other v1: 5075.37,1115.32
5V0_IMAGE_1: C140.1 C141.1 J18.1 J18.2 J18.3 U29.1
5V0_IMAGE_2: C137.1 C138.1 J19.1 J19.2 J19.3 U30.1
5V_OUT: C48.1 C49.1 J3.3 U7.1 | length 279
  BOTTOM w12: C49.1@260,1245.32 C48.1@310,1245.32 312.28,1247.6 U7.1@375.79,1247.6
  BOTTOM w15: J3.3@98.74,1247.8 101.22,1245.32 C49.1@260,1245.32
12V_EDP: C166.1 C167.1 J22.26 J22.27 J22.28 J22.29 Q13.3 | length 330.9
  TOP w12: 5034.75,961.7 J22.26@5117.47,961.7 ; 5034.75,981.38 J22.27@5117.47,981.38 ; 5034.75,1001.07 J22.28@5117.47,1001.07 ; 5034.75,1020.75 J22.29@5117.47,1020.75
12V_OUT: C39.1 C40.1 J3.1 Q5.3 | length 313.7
  BOTTOM w20: J3.1@98.74,1405.28 123.14,1429.68 C40.1@250,1429.68 261.82,1441.5 C39.1@300,1441.5 321.5,1420 Q5.3@388.5,1420
B_DM1: J15.11 R130.1 U18.5 U18.6 | length 1065.7
  BOTTOM w6.23: R130.1@3550,3090.32 3570.63,3069.69 U18.6@3570.63,3040.75 U18.5@3570.63,3009.25 3570.63,2988.61 3573.35,2985.89 3573.35,2955.34 3412.24,2794.23 3379.1,2794.23 3344.8,2759.93 3344.8,2733.84 3330.77,2719.81 3330.77,2644.1 3377.1,2597.77 3612.78,2597.77 3654.23,2639.22 3654.23,2680 3697.42,2723.19 J15.11@3725.66,2723.19
B_DM2: J17.8 R139.1 U20.4 U20.7 | length 307.1
  BOTTOM w6.23: R139.1@4415,3055.32 4415.31,3055.01 U20.7@4415.31,2985.75 U20.4@4415.31,2954.25 4415.31,2933.62 4412.58,2930.89 4412.58,2902.42 4442.21,2872.79 4442.21,2807.41 J17.8@4474.47,2775.15
B_DM3: J17.2 R132.1 U20.1 U20.10 | length 511.3
  BOTTOM w6.23: J17.2@4474.47,2657.04 4442.21,2689.3 4442.21,2698.12 4449.09,2705 4498,2705 4531,2738 4531,2859 4471.64,2918.36 4471.64,2930.89 4474.37,2933.62 U20.1@4474.37,2954.25 U20.10@4474.37,2985.75 4474.37,3034.69 R132.1@4495,3055.32
B_DP1: J15.12 R131.1 U18.4 U18.7 | length 1030.8
  BOTTOM w6.23: R131.1@3590,3090.32 3590,3041.06 U18.7@3590.31,3040.75 U18.4@3590.31,3009.25 3590.31,2988.62 3587.58,2985.89 3587.58,2949.44 3418.14,2780 3385,2780 3359.03,2754.03 3359.03,2727.94 3345,2713.91 3345,2650 3383,2612 3400.53,2612 ccw(c3400.53,2619) 3407.53,2619 cw(c3414.53,2619) 3414.53,2626 3425.45,2626 cw(c3425.45,2619) 3432.45,2619 ccw(c3439.45,2619) 3439.45,2612 3450.37,2612 ccw(c3450.37,2619) 3457.37,2619 cw(c3464.37,2619) 3464.37,2626 3475.29,2626 cw(c3475.29,2619) 3482.29,2619 ccw(c3489.29,2619) 3489.29,2612 3500.21,2612 ccw(c3500.21,2619) 3507.21,2619 cw(c3514.21,2619) 3514.21,2626 3525.13,2626 cw(c3525.13,2619) 3532.13,2619 ccw(c3539.13,2619) 3539.13,2612 3550.05,2612 ccw(c3550.05,2619) 3557.05,2619 cw(c3564.05,2619) 3564.05,2626 3574.97,2626 cw(c3574.97,2619) 3581.97,2619 ccw(c3588.97,2619) 3588.97,2612 3606.88,2612 3640,2645.12 3640,2716.27 J15.12@3646.92,2723.19
B_DP2: J17.9 R140.1 U20.5 U20.6 | length 315.5
  BOTTOM w6.23: R140.1@4375,3055.32 4395.63,3034.69 U20.6@4395.63,2985.75 U20.5@4395.63,2954.25 4395.63,2933.61 4398.35,2930.89 4398.35,2896.52 4427.98,2866.89 4427.98,2807.4 J17.9@4395.73,2775.15
B_DP3: J17.3 R133.1 U20.2 U20.9 | length 502.9
  BOTTOM w6.23: J17.3@4395.73,2657.04 4427.98,2689.29 4427.98,2704.02 4443.19,2719.23 4492.1,2719.23 4516.77,2743.9 4516.77,2853.1 4457.41,2912.46 4457.41,2930.89 4454.69,2933.61 U20.2@4454.69,2954.25 U20.9@4454.69,2985.75 4454.69,3055.01 R133.1@4455,3055.32
BD_CH3: C56.1 J30.204 R35.2 R36.1 | length 363.8
  TOP w6.16: R35.2@1085,1489.68 1107,1511.68 1107,1562.68 R36.1@1085,1584.68 1107,1606.68 1107,1657.68 C56.1@1085,1679.68 1092.98,1687.66 J30.204@1092.98,1813.7
CAM0_NRST: J20.22 J30.25 | length 2865.3
  TOP w6.16: v1(2933.52,2078.07) J30.25@2933.54,2136.54
  BOTTOM w6.16: v1(2933.52,2078.07) 2933.52,2258.52 2955,2280 3352.68,2280 3365,2292.32 3365,2465 3380,2480 3575,2480 3695,2600 4065,2600 4085,2580 4235,2580 4260,2605 4590,2605 4615,2630 4615,2765 4635,2785 4846.99,2785 4869.98,2762.01 J20.22@5135.46,2762.01
CAM0_PWDN: J20.15 J30.26 | length 4098.1
  TOP w6.16: J30.26@2923.7,1813.7 2923.7,1671.3 3000,1595 3000,1443.7 3033.04,1410.66 3061.24,1410.66 v1(3080.32,1391.58)
  ART03 w5.61: v1(3080.32,1391.58) 3115.58,1391.58 3157,1433 3463,1433 3536,1506 4505.01,1506 4572.01,1573 4698.26,1573 v1(4717.63,1553.63)
  ART04 w5.61: v1(4717.63,1553.63) 4775.63,1553.63 4814,1592 4955,1592 4990,1627 4990,2010.78 5001.22,2022 5094.78,2022 5106,2033.22 5106,2416.78 5117.22,2428 5325.2,2428 5336.42,2416.78 v1(5336.42,2371.69)
  BOTTOM w6.16: J20.15@5135.46,2624.21 5188.79,2624.21 5206,2607 5252,2607 5262,2597 5262,2452.99 5336.42,2378.57 v1(5336.42,2371.69)
CAM0_PWR_EN: J30.6 R180.1 | length 5411.3
  TOP w6.16: J30.6@3120.55,1813.7 3120.55,1739.45 3140,1720 3335,1720 3401,1654 3401,993 v1(3395,987) ; v1(4596.6,2017.4) R180.1@4625.32,2017.4
  ART03 w5.61: v1(3395,987) 3402.95,979.05 3695.95,979.05 3718,957 4443,957 4456,944 4456,614.22 4467.22,603 4720,603 4810,513 4810,391 4824,377 5086.99,377 5115,405.01 5115,633.39 5103.39,645 5022.01,645 5012,655.01 5012,1045.31 v1(5017.75,1051.06)
  BOTTOM w6.16: v1(4596.6,2017.4) 4611.6,2002.4 4611.6,1682.4 4627,1667 4959,1667 4983,1643 4983,1085.81 v1(5017.75,1051.06)
CAM1_NRST: J21.22 J30.23 | length 3567
  TOP w6.16: J30.23@2953.22,2136.54 2953.22,2058.37 v1(2972.89,2038.7)
  BOTTOM w6.16: v1(2972.89,2038.7) 2953.81,2057.78 2953.81,2238.81 2975,2260 3377.68,2260 3390,2272.32 3390,2442.68 3402.32,2455 3585,2455 3710,2580 4035,2580 4085,2530 4242,2530 4294,2582 4571,2582 4598,2555 4704.68,2555 4717,2542.68 4717,2427 4781,2363 4781,2159 4772,2150 4743.16,2150 4737,2143.84 4737,1966 4757.87,1945.13 5044.33,1945.13 5055.5,1956.3 5055.5,2092.51 5065,2102.01 J21.22@5135.46,2102.01
CAM1_PWDN: J21.15 J30.16 | length 3045.3
  TOP w6.16: J30.16@3022.13,1813.7 3022.13,1712.87 3095,1640 3287.84,1640 3317.84,1610 3317.84,1356.92 v1(3315.92,1355)
  ART03 w5.61: v1(3315.92,1355) 3490.01,1355 3530.01,1395 4501,1395 4529,1423 4568,1423 4576,1431 4576,1471 4596,1491 4694.37,1491 v1(4717.63,1514.26)
  ART04 w5.61: v1(4717.63,1514.26) 4808.26,1514.26 4839,1545 4985,1545 5012,1572 5012,1975.55 5023.22,1986.77 5053.23,1986.77 v1(5075.79,1964.21)
  BOTTOM w6.16: v1(5075.79,1964.21) J21.15@5135.46,1964.21
CAM1_PWR_EN: J30.49 R187.1 | length 2876.8
  TOP w6.16: v1(2697.3,2078.07) J30.49@2697.32,2136.54 ; v1(4320.26,1148) 4343.26,1125 4394,1125 4405,1114 4405,1058.16 4417.16,1046 4622.84,1046 4635,1058.16 4635,1132.72 R187.1@4620.32,1147.4
  ART03 w5.61: v1(3290,1224) 3358,1224 3434,1148 v1(4320.26,1148)
  BOTTOM w6.16: v1(2697.3,2078.07) 2697.3,2065.69 2716.38,2046.61 2716.38,1998.62 2906,1809 3191,1809 3232,1768 3232,1653 3285,1600 3285,1229 v1(3290,1224)
CC1: D26.2 J16.A5 | length 202.4
  TOP w6.16: v1(1102.5,2867) 1125.13,2889.63 J16.A5@1125.13,2953.48
  BOTTOM w6.16: v1(1102.5,2867) D26.2@1102.5,2973.5
CC2: D26.1 J16.B5 | length 201.5
  TOP w6.16: J16.B5@1007.03,2953.48 1007.03,2887.47 v1(1027.5,2867)
  BOTTOM w6.16: v1(1027.5,2867) D26.1@1027.5,2973.5
CSI_RX_D2N_S0: J20.17 R179.2 | length 374.7
  BOTTOM w4.88: R179.2@4845,2559.68 4845,2577.5 4858.56,2591.06 4858.56,2643.56 4875.18,2660.18 5098.97,2660.18 5102.37,2663.58 J20.17@5135.46,2663.58
CSI_RX_D2N_S1: J21.12 R181.2 | length 1268.4
  ART03 w4.44: v1(4875.31,2218) 4887.34,2205.97 4887.34,1960.06 4912.05,1935.35 5102.72,1935.35 5114.44,1947.07 5114.44,2112.12 5121.88,2119.56 5146.12,2119.56 5153.56,2112.12 5153.56,1960.84 5189.49,1924.91 5189.62,1924.91 5189.62,1918.62 v1(5176.16,1905.16)
  BOTTOM w4.88: R181.2@4845,2480.32 4845,2462.5 4858.56,2448.94 4858.56,2423.22 4887.12,2394.66 4887.12,2229.81 v1(4875.31,2218) ; J21.12@5135.46,1905.16 v1(5176.16,1905.16)
CSI_RX_D2P_S0: J20.16 R177.2 | length 409.5
  BOTTOM w4.88: R177.2@4885,2559.68 4885,2577.5 4871.44,2591.06 4871.44,2638.22 4880.52,2647.3 4897.4,2647.3 cw(c4897.4,2641.15) 4903.55,2641.15 ccw(c4909.7,2641.15) 4909.7,2635 4916.92,2635 ccw(c4916.92,2641.15) 4923.07,2641.15 cw(c4929.22,2641.15) 4929.22,2647.3 4936.44,2647.3 cw(c4936.44,2641.15) 4942.59,2641.15 ccw(c4948.74,2641.15) 4948.74,2635 4955.96,2635 ccw(c4955.96,2641.15) 4962.11,2641.15 cw(c4968.26,2641.15) 4968.26,2647.3 4975.48,2647.3 cw(c4975.48,2641.15) 4981.63,2641.15 ccw(c4987.78,2641.15) 4987.78,2635 4995,2635 ccw(c4995,2641.15) 5001.15,2641.15 cw(c5007.3,2641.15) 5007.3,2647.3 5014.52,2647.3 cw(c5014.52,2641.15) 5020.67,2641.15 ccw(c5026.82,2641.15) 5026.82,2635 5034.04,2635 ccw(c5034.04,2641.15) 5040.19,2641.15 cw(c5046.34,2641.15) 5046.34,2647.3 5098.97,2647.3 5102.37,2643.9 J20.16@5135.46,2643.9
CSI_RX_D2P_S1: J21.11 R178.2 | length 1315.9
  ART03 w4.44: v1(4911.82,2218) 4899.78,2205.96 4899.78,1965.22 4917.21,1947.79 5097.56,1947.79 5102,1952.23 5102,2117.28 5116.72,2132 5151.28,2132 5166,2117.28 5166,1966 5194.65,1937.35 5194.78,1937.35 5202.06,1930.07 5202.06,1918.63 v1(5215.53,1905.16)
  BOTTOM w4.88: R178.2@4885,2480.32 4885,2462.5 4871.44,2448.94 4871.44,2428.56 4900,2400 4900,2229.82 v1(4911.82,2218) ; J21.11@5135.46,1885.47 5195.84,1885.47 v1(5215.53,1905.16)
CSI_RX_D3N_S0: J20.20 R185.2 | length 513.3
  BOTTOM w4.88: R185.2@4765,2559.68 4765,2577.5 4778.56,2591.06 4778.56,2701.78 4796.01,2719.23 5098.97,2719.23 5102.38,2722.64 J20.20@5135.46,2722.64
CSI_RX_D3N_S1: J21.8 R186.2 | length 1400
  ART03 w4.44: v1(4782.31,2028) 4794.34,2015.97 4794.34,1843.06 4808.4,1829 4828.16,1829 4840.64,1841.48 4840.64,1872.36 4845.84,1877.56 4853.2,1877.56 4858.4,1872.36 4858.4,1841.48 4870.88,1829 4888.56,1829 4901.04,1841.48 4901.04,1872.36 4906.24,1877.56 4913.6,1877.56 4918.8,1872.36 4918.8,1841.48 4931.28,1829 4948.96,1829 4961.44,1841.48 4961.44,1872.36 4966.64,1877.56 4974,1877.56 4979.2,1872.36 4979.2,1841.48 4991.68,1829 5103,1829 5135.56,1861.56 5185.18,1861.56 5189.62,1857.12 5189.62,1839.88 v1(5176.16,1826.42)
  BOTTOM w4.88: R186.2@4765,2480.32 4765,2462.5 4778.56,2448.94 4778.56,2415.22 4816.12,2377.66 4816.12,2110.34 4794.12,2088.34 4794.12,2039.81 v1(4782.31,2028) ; J21.8@5135.46,1826.42 v1(5176.16,1826.42)
CSI_RX_D3P_S0: J20.19 R183.2 | length 527.4
  BOTTOM w4.88: R183.2@4805,2559.68 4805,2577.5 4791.44,2591.06 4791.44,2696.44 4801.35,2706.35 4907.42,2706.35 cw(c4907.42,2701.18) 4912.59,2701.18 ; 4912.59,2701.17 ccw(c4917.76,2701.17) 4917.76,2696 4926.94,2696 ccw(c4926.94,2701.17) 4932.11,2701.17 ; 4932.11,2701.18 cw(c4937.28,2701.18) 4937.28,2706.35 4946.46,2706.35 cw(c4946.46,2701.18) 4951.63,2701.18 ; 4951.63,2701.17 ccw(c4956.8,2701.17) 4956.8,2696 4965.98,2696 ccw(c4965.98,2701.17) 4971.15,2701.17 ; 4971.15,2701.18 cw(c4976.32,2701.18) 4976.32,2706.35 4985.5,2706.35 cw(c4985.5,2701.18) 4990.67,2701.18 ; 4990.67,2701.17 ccw(c4995.84,2701.17) 4995.84,2696 5005.02,2696 ccw(c5005.02,2701.17) 5010.19,2701.17 ; 5010.19,2701.18 cw(c5015.36,2701.18) 5015.36,2706.35 5098.97,2706.35 5102.37,2702.95 J20.19@5135.46,2702.95
CSI_RX_D3P_S1: J21.7 R184.2 | length 1447.6
  ART03 w4.44: v1(4818.82,2028) 4806.78,2015.96 4806.78,1848.22 4813.56,1841.44 4823,1841.44 4828.2,1846.64 4828.2,1877.52 4840.68,1890 4858.36,1890 4870.84,1877.52 4870.84,1846.64 4876.04,1841.44 4883.4,1841.44 4888.6,1846.64 4888.6,1877.52 4901.08,1890 4918.76,1890 4931.24,1877.52 4931.24,1846.64 4936.44,1841.44 4943.8,1841.44 4949,1846.64 4949,1877.52 4961.48,1890 4979.16,1890 4991.64,1877.52 4991.64,1846.64 4996.84,1841.44 5097.84,1841.44 5130.4,1874 5190.34,1874 5202.06,1862.28 5202.06,1839.89 v1(5215.53,1826.42)
  BOTTOM w4.88: R184.2@4805,2480.32 4805,2462.5 4791.44,2448.94 4791.44,2420.56 4829,2383 4829,2105 4807,2083 4807,2039.82 v1(4818.82,2028) ; J21.7@5135.46,1806.73 5195.84,1806.73 v1(5215.53,1826.42)
CTP0_INT: J18.11 J30.30 R163.2 | length 3574.1
  TOP w6.16: J30.30@2884.33,1813.7 2884.33,1655.67 2935,1605 2935,1427.32 2991.03,1371.29 3061.24,1371.29 v1(3080.32,1352.21) ; R163.2@5006.68,2435 v1(5036,2435) 5064.58,2406.42 J18.11@5117.47,2406.42
  ART03 w5.61: v1(3080.32,1352.21) 3142.21,1352.21 3189,1399 3479,1399 3515,1435 4489,1435 4584,1530 4654.63,1530 v1(4678.26,1553.63)
  ART04 w5.61: v1(4678.26,1553.63) 4699.63,1575 4772,1575 4835,1638 4941,1638 4972,1669 4972,2049.78 4983.22,2061 5047,2061 5054,2068 5054,2417 v1(5036,2435)
CTP0_RST: J18.12 J30.34 R167.2 | length 4198
  TOP w6.16: J30.34@2844.96,1813.7 2844.96,1660.04 2915,1590 v1(2915,1395) ; J18.12@5117.47,2426.11 5171.44,2426.11 5172.09,2426.76 5205.34,2426.76 5218.31,2413.79 v1(5218.31,2371.69)
  ART03 w5.61: v1(2915,1395) 3001,1395 3015,1409 3015,1512 3033,1530 3455,1530 3532,1607 4016,1607 4053,1570 4464,1570 4552,1658 4761,1658 4831,1728 5280.75,1728 v1(5300.43,1747.68)
  ART04 w5.61: v1(5218.31,2371.69) 5236,2354 5236,2321.01 5304,2253.01 5304,1751.25 v1(5300.43,1747.68)
  BOTTOM w6.16: R167.2@5040.32,2275 5017.32,2275 5005,2287.32 5005,2312.68 5017.32,2325 5028.15,2325 5028.23,2324.92 5164.92,2324.92 5175,2335 5175,2360 5186.69,2371.69 v1(5218.31,2371.69)
CTP1_INT: J19.11 J30.33 R165.2 | length 3130.4
  TOP w6.16: v1(2854.78,2078.07) J30.33@2854.8,2136.54 ; R165.2@4864.68,1615 4895.63,1584.05 v1(4895.63,1573.01) 4900.62,1568.02 4919.51,1549.12 5039.88,1549.12 5052.58,1536.42 J19.11@5117.47,1536.42
  ART03 w5.61: v1(3530,1340) 3555,1365 4803.99,1365 4869,1430.01 4869,1546.38 v1(4895.63,1573.01)
  BOTTOM w6.16: v1(2854.78,2078.07) 2875.07,2057.78 2875.07,2013.93 2982,1907 3255.37,1907 3335,1827.37 3335,1740.01 3395.01,1680 3517.68,1680 3530,1667.68 v1(3530,1340)
CTP1_RST: J19.12 J30.31 R169.2 | length 3304.7
  TOP w6.16: J30.31@2874.48,2136.54 2874.48,2058.37 v1(2894.15,2038.7) ; R169.2@5006.68,1570 v1(5036,1570) 5049,1570 5062.89,1556.11 J19.12@5117.47,1556.11
  ART03 w5.61: v1(3570,1300.01) 3599.99,1330 4857,1330 4874,1347 5087,1347 5097,1357 5097,1558.78 5085.78,1570 v1(5036,1570)
  BOTTOM w6.16: v1(2894.15,2038.7) 2894.15,2021.84 2992.99,1923 3262,1923 3351,1834 3351,1749 3402.5,1697.5 3552.5,1697.5 3570,1680 v1(3570,1300.01)
DBG_RX: R41.2 U10.2 | length 68.5
  BOTTOM w6.16: U10.2@285.31,769.57 285.31,714.37 R41.2@294.68,705
DBG_RXD: J6.3 R41.1 Z3.1 | length 176
  BOTTOM w6.16: J6.3@120,666.54 121.54,665 Z3.1@255.32,665 R41.1@255.32,705
DBG_TX: R40.2 U9.4 | length 172.4
  BOTTOM w6.16: R40.2@294.68,570 378.84,570 385,563.84 385,531.43 378.84,525.27 U9.4@340.43,525.27
DBG_TXD: J6.2 R40.1 Z2.1 | length 193.3
  BOTTOM w6.16: J6.2@120,566.54 163.46,610 Z2.1@255.32,610 R40.1@255.32,570
DM4: D35.2 J24.36 R213.1 | length 162.9
  TOP w6.23: J24.36@3889.82,2168.04 3889.82,2122.37 3881.19,2113.74 3881.19,2069.13 D35.2@3895.32,2055 3895,2054.68 R213.1@3895,2014.68
DP4: D36.2 J24.38 R214.1 | length 162.2
  TOP w6.23: R214.1@3855,2014.68 3855,2054.68 D36.2@3854.68,2055 3866.96,2067.28 3866.96,2113.74 3858.33,2122.37 J24.38@3858.33,2168.04
DSI0_RST: J18.15 J30.24 | length 3813.1
  TOP w6.16: J30.24@2943.39,1813.7 2943.39,1681.61 3020,1605 3020,1451.9 v1(3040.95,1430.95) ; J18.15@5117.47,2485.16 5230.47,2485.16 5277.36,2438.27 5277.36,2352 v1(5257.68,2332.32)
  ART03 w5.61: v1(3040.95,1430.95) 3040.95,1485.95 3047.87,1492.87 3442.87,1492.87 3540,1590 3998,1590 4033,1555 4474,1555 4562,1643 4767.22,1643 4836.22,1712 5296.74,1712 v1(5300.43,1708.31)
  ART04 w5.61: v1(5257.68,2332.32) 5320,2270 5320,1727.88 v1(5300.43,1708.31)
DSI0_TE: J30.22 R161.1 | length 3635.3
  TOP w6.16: J30.22@2963.07,1813.7 2963.07,1686.93 3040,1610 3040,1471.27 v1(3080.32,1430.95)
  ART03 w5.61: v1(3080.32,1430.95) 3121.37,1472 3447,1472 3546.49,1571.49 3992.51,1571.49 4025,1539 4487,1539 4572,1624 4784,1624 4834,1674 5295.37,1674 v1(5300.43,1668.94)
  ART04 w5.61: v1(5036.42,1964.21) 5036.42,1820.61 5048.03,1809 5264,1809 5280,1793 5280,1689.37 v1(5300.43,1668.94)
  BOTTOM w6.16: v1(5036.42,1964.21) 5017.32,1964.21 5005,1976.53 5005,2222.68 5017.32,2235 R161.1@5040.32,2235
DSI1_RST: J19.15 J30.35 | length 3333.2
  TOP w6.16: J30.35@2835.11,2136.54 2835.11,2058.37 v1(2854.78,2038.7) ; J19.15@5117.47,1615.16 v1(5180,1615.16)
  ART03 w5.61: v1(3530,1300) 3580,1350 4842.01,1350 4917,1424.99 4917,1638 4933,1654 5141.16,1654 v1(5180,1615.16)
  BOTTOM w6.16: v1(2854.78,2038.7) 2854.78,2001.22 2965,1891 3248.74,1891 3319,1820.74 3319,1726 3390,1655 3462.68,1655 3475,1642.68 3475,1355 v1(3530,1300)
DSI1_TE: J30.37 R162.1 | length 3486.3
  TOP w6.16: v1(2815.41,2078.07) J30.37@2815.43,2136.54 ; v1(4938,1615) R162.1@4967.32,1615
  ART03 w5.61: v1(3530,1265) 3575,1265 3600,1290 4863,1290 4877,1304 5102.99,1304 5121,1322.01 5121,1603.78 5109.78,1615 v1(4938,1615)
  BOTTOM w6.16: v1(2815.41,2078.07) 2834.49,2058.99 2834.49,1992.51 2951,1876 3234,1876 3304,1806 3304,1706 3375,1635 3442.68,1635 3455,1622.68 3455,1340 v1(3530,1265)
EDP_AUXN: C157.2 J22.10 R192.2 | length 156
  TOP w4.88: R192.2@5007.68,695 C157.2@5007.68,655 5019.35,643.33 5080.98,643.33 5084.39,646.74 J22.10@5117.47,646.74
EDP_AUXP: C156.2 J22.9 R189.2 | length 157.6
  TOP w4.88: R189.2@5007.68,575 C156.2@5007.68,615 5023.13,630.45 5080.98,630.45 5084.38,627.05 J22.9@5117.47,627.05
EDP_BL_EN: J22.22 J30.136 | length 5421.8
  TOP w6.16: v1(1838.11,909.37) 1841.02,912.28 J30.136@1841.02,1813.7 ; v1(5068.63,882.96) J22.22@5117.47,882.96
  ART03 w5.61: v1(1838.11,909.37) 1856.74,928 1921,928 1945.49,903.51 3323.49,903.51 3369,858 4341,858 4369,830 4369,568 4390,547 4714,547 4774,487 4774,363 4793,344 5178.99,344 5201,366.01 5201,703.99 5184.99,720 5103.22,720 5092,731.22 5092,859.59 v1(5068.63,882.96)
EDP_BL_PWM: J22.23 J30.167 | length 6637.4
  TOP w6.16: J30.167@1457.16,2136.54 1457.16,2058.38 v1(1476.84,2038.7) ; v1(1663.85,225) v1(1663.85,1676.49) ; J22.23@5117.47,902.64 v1(5181.46,902.64)
  ART03 w5.61: v1(1476.84,2038.7) 1476.84,1967.16 1490,1954 1674,1954 1703,1925 1703,1715.64 v1(1663.85,1676.49) ; v1(1663.85,225) 1698.85,260 2845,260 2881.81,223.19 3303.19,223.19 3325,245 3720,245 3740,225 4654.99,225 4729.99,300 5111,300 5136,325 5239.99,325 5286,371.01 5286,728.39 5269.39,745 5146,745 5135,756 5135,891.42 5146.22,902.64 v1(5181.46,902.64)
EDP_HPDIN_M0: J22.17 J30.45 | length 4964.4
  TOP w6.16: v1(2736.67,2078.07) J30.45@2736.69,2136.54 ; J22.17@5117.47,784.53 5201.15,784.53 v1(5220.83,764.85)
  ART03 w5.61: v1(3355,225) 3710,225 3730,205 4665,205 4739.99,279.99 5120,279.99 5142.01,302 5247.99,302 5304,358.01 5304,753.24 5292.39,764.85 v1(5220.83,764.85)
  BOTTOM w6.16: v1(2736.67,2078.07) 2755.75,2058.99 2755.75,1989.25 2920,1825 3200,1825 3251,1774 3251,1669 3335,1585 3335,1100 3314.08,1079.08 3314.08,265.92 v1(3355,225)
EDP_PWR_EN: J30.8 R193.1 R198.1 | length 3477.5
  TOP w6.16: J30.8@3100.87,1813.7 3100.87,1734.12 3134.99,1700 3330,1700 3385,1645 3385,1037 3333,985 3333,953 v1(3335,951) ; v1(4420.27,646.26) 4488.26,646.26 4506,664 4506,732 4521,747 4639.99,747 4656.99,730 R198.1@4720.32,730
  ART03 w5.61: v1(2780,990) 3245,990 3284,951 v1(3335,951) 3384,902 3692,902 3713,923 4384.99,923 4402,905.99 4402,664.53 v1(4420.27,646.26)
  BOTTOM w6.16: R193.1@2780,959.68 v1(2780,990)
EDP_TP_INT: J23.2 J30.12 R190.2 | length 2963.8
  TOP w6.16: J23.2@2441.46,105.01 2540,203.55 R190.2@2540,285.32 ; J30.12@3061.5,1813.7 3061.5,1723.5 3115,1670 3310.01,1670 3350,1630.01 3350,1112.15 3262.69,1024.84 v1(3262.69,245)
  BOTTOM w6.16: J23.2@2441.46,105.01 2526.45,190 3065,190 3150,275 3232.69,275 v1(3262.69,245)
EDP_TP_RESET: J23.3 J30.14 R191.2 | length 2806.1
  TOP w6.16: J23.3@2520.2,105.01 2580,164.81 R191.2@2580,285.32 ; J30.14@3041.81,1813.7 3041.81,1718.2 3105.01,1655 3300,1655 3335,1620 3335,1125 3243,1033 3243,283 v1(3205,245)
  BOTTOM w6.16: J23.3@2520.2,105.01 2580.19,165 3085,165 3165,245 v1(3205,245)
EDP_TX_AUXN: C157.1 J30.209 | length 5902.9
  TOP w4.88: J30.209@1043.78,2136.54 1043.78,2089.68 1040.37,2086.27 1040.37,2003.88 1052.25,1992 1074.01,1992 1081.95,1999.94 v1(1081.95,2007.82) ; v1(4899.64,653.25) 4911.45,641.44 4954.76,641.44 C157.1@4968.32,655
  ART03 w4.44: v1(1081.95,2007.82) 1081.95,1994.22 1086.39,1989.78 1136.22,1989.78 1224.56,1901.44 1628.84,1901.44 1645,1885.28 1645,1484.6 1887.16,1242.44 2277.84,1242.44 2362.84,1327.44 2607.56,1327.44 2646.36,1288.64 3199.04,1288.64 3229.84,1319.44 3442.56,1319.44 3521.56,1240.44 4413.16,1240.44 4437.54,1216.06 4767.94,1216.06 4833,1151 4833,891.5 4838.2,886.3 4931.52,886.3 4944,873.82 4944,856.14 4931.52,843.66 4838.2,843.66 4833,838.46 4833,831.1 4838.2,825.9 4931.52,825.9 4944,813.42 4944,795.74 4931.52,783.26 4838.2,783.26 4833,778.06 4833,770.7 4838.2,765.5 4931.52,765.5 4944,753.02 4944,735.34 4931.52,722.86 4838.2,722.86 4833,717.66 4833,657.01 4855.8,634.21 4890.17,634.21 4899.64,643.68 v1(4899.64,653.25)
